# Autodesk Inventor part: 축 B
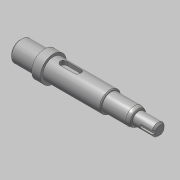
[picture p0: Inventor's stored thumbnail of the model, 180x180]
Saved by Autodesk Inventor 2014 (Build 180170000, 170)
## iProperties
Created: 2020-04
Part Number: 축 B
Material: 강철, 연강
Document SubType Name: Modeling
Designer: mduedu
Density: 7.86 g/cm^3
Appearance: Steel
Mass: 60.8547 g
Surface Area: 31.2855 cm^2
Volume: 7.74232 cm^3
Author: mduedu
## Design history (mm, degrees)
sketch "스케치1"
  geometry: L1 (0, 0)-(14, 0); L2 (14, 0)-(14, 6); L3 (14, 6)-(0, 6); L4 (0, 6)-(0, 0); L5 (14, 0)-(19, 0); L6 (19, 0)-(19, 7.5); L7 (19, 7.5)-(14, 7.5); L8 (14, 7.5)-(14, 0); L9 (19, 0)-(52, 0); L10 (52, 0)-(52, 6); L11 (52, 6)-(19, 6); L12 (19, 6)-(19, 0); L13 (52, 0)-(68, 0); L14 (68, 0)-(68, 5); L15 (68, 5)-(52, 5); L16 (52, 5)-(52, 0); L17 (68, 0)-(80, 0); L18 (80, 0)-(80, 3.5); L19 (80, 3.5)-(68, 3.5); L20 (68, 3.5)-(68, 0)
  constraints: 40 end point, 10 parallel, 5 horizontal, 5 perpendicular
  dimensions: "d0" = 80 distance between parallel lines of L18 L4; "d2" = 14 distance of L2.end L3.end; "d3" = 5 distance of L6.end L7.end; "d5" = 7 diameter of L19 L17; "d6" = 10 diameter of L15 L13; "d7" = 12 diameter of L11 L9; "d8" = 12 diameter of L3 L1; "d9" = 15 diameter of L7 L5; "d35" = 16 distance of L14.end L15.end; "d36" = 52 distance between parallel lines of L10 L4
revolve "회전1" sketch "스케치1" stored, may be unused: angle "d11" = 90 deg
sketch "스케치2"
  geometry: L1 (0, 6)-(0, -6) reference; L2 (0, -6)-(-14, -6) reference; L3 (-14, -6)-(-14, -7.5) reference; L4 (-14, -7.5)-(-19, -7.5) reference; L5 (-19, -7.5)-(-19, -6) reference; L6 (-19, -6)-(-52, -6) reference; L7 (-52, -6)-(-52, -5) reference; L8 (-52, -5)-(-68, -5) reference; L9 (-68, -5)-(-68, -3.5) reference; L10 (-68, -3.5)-(-80, -3.5) reference; L11 (-80, -3.5)-(-80, 3.5) reference; L12 (-80, 3.5)-(-68, 3.5) reference; L13 (-68, 3.5)-(-68, 5) reference; L14 (-68, 5)-(-52, 5) reference; L15 (-52, 5)-(-52, 6) reference; L16 (-52, 6)-(-19, 6) reference; L17 (-19, 6)-(-19, 7.5) reference; L18 (-19, 7.5)-(-14, 7.5) reference; L19 (-14, 7.5)-(-14, 6) reference; L20 (-14, 6)-(0, 6) reference; L21 (-80, 3.5)-(-72, 3.5); L22 (-72, 3.5)-(-72, 2.3); L23 (-72, 2.3)-(-80, 2.3); L24 (-80, 2.3)-(-80, 3.5); 1 further point
  constraints: 8 end point, 2 parallel, 1 horizontal, 1 perpendicular
  dimensions: "d37" = 8 distance of L22.end L23.end; "d38" = 1.2 distance of L21.end L22.end
extrude "돌출1" cut sketch "스케치2" stored distance "d14" = 2; taper "d15" = 0 deg
fillet "모깎기1" dims "d16" = 1
sketch "스케치3"
  geometry: L1 (0, -6)-(0, 6) reference; L2 (0, 6)-(14, 6) reference; L3 (14, 6)-(14, 7.5) reference; L4 (14, 7.5)-(19, 7.5) reference; L5 (19, 7.5)-(19, 6) reference; L6 (19, 6)-(52, 6) reference; L7 (52, 6)-(52, 5) reference; L8 (52, 5)-(68, 5) reference; L9 (68, 5)-(68, 3.5) reference; L10 (68, 3.5)-(80, 3.5) reference; L11 (80, 3.5)-(80, -3.5) reference; L12 (80, -3.5)-(68, -3.5) reference; L13 (68, -3.5)-(68, -5) reference; L14 (68, -5)-(52, -5) reference; L15 (52, -5)-(52, -6) reference; L16 (52, -6)-(19, -6) reference; L17 (19, -6)-(19, -7.5) reference; L18 (19, -7.5)-(14, -7.5) reference; L19 (14, -7.5)-(14, -6) reference; L20 (14, -6)-(0, -6) reference; L21 (23, 6)-(35, 6); L22 (35, 6)-(35, 3.5); L23 (35, 3.5)-(23, 3.5); L24 (23, 3.5)-(23, 6); 1 further point
  constraints: 8 end point, 2 parallel, 1 horizontal, 1 perpendicular, 1 point on line
  dimensions: "d17" = 12 distance of L22.end L23.end; "d18" = 2.5 distance of L21.end L22.end; "d19" = 4 distance from line of L24 L4.end
extrude "돌출2" cut sketch "스케치3" stored distance "d20" = 4; taper "d21" = 0 deg
fillet "모깎기2" dims "d22" = 2
chamfer "모따기1" distance "d23" = 1; stored, may be unused: second distance "d24" = 2, angle "d25" = 45 deg
chamfer "모따기2" distance "d26" = 0.5; stored, may be unused: second distance "d27" = 2, angle "d28" = 45 deg
fillet "모깎기3" dims "d29" = 0.3
chamfer "모따기3" distance "d30" = 1.39; stored, may be unused: second distance "d31" = 2, angle "d32" = 30 deg
fillet "모깎기4" dims "d33" = 4, "d34" = 0.5
node "솔리드1"
node "절단 모서리 투영2"
node "절단 모서리 투영3"
